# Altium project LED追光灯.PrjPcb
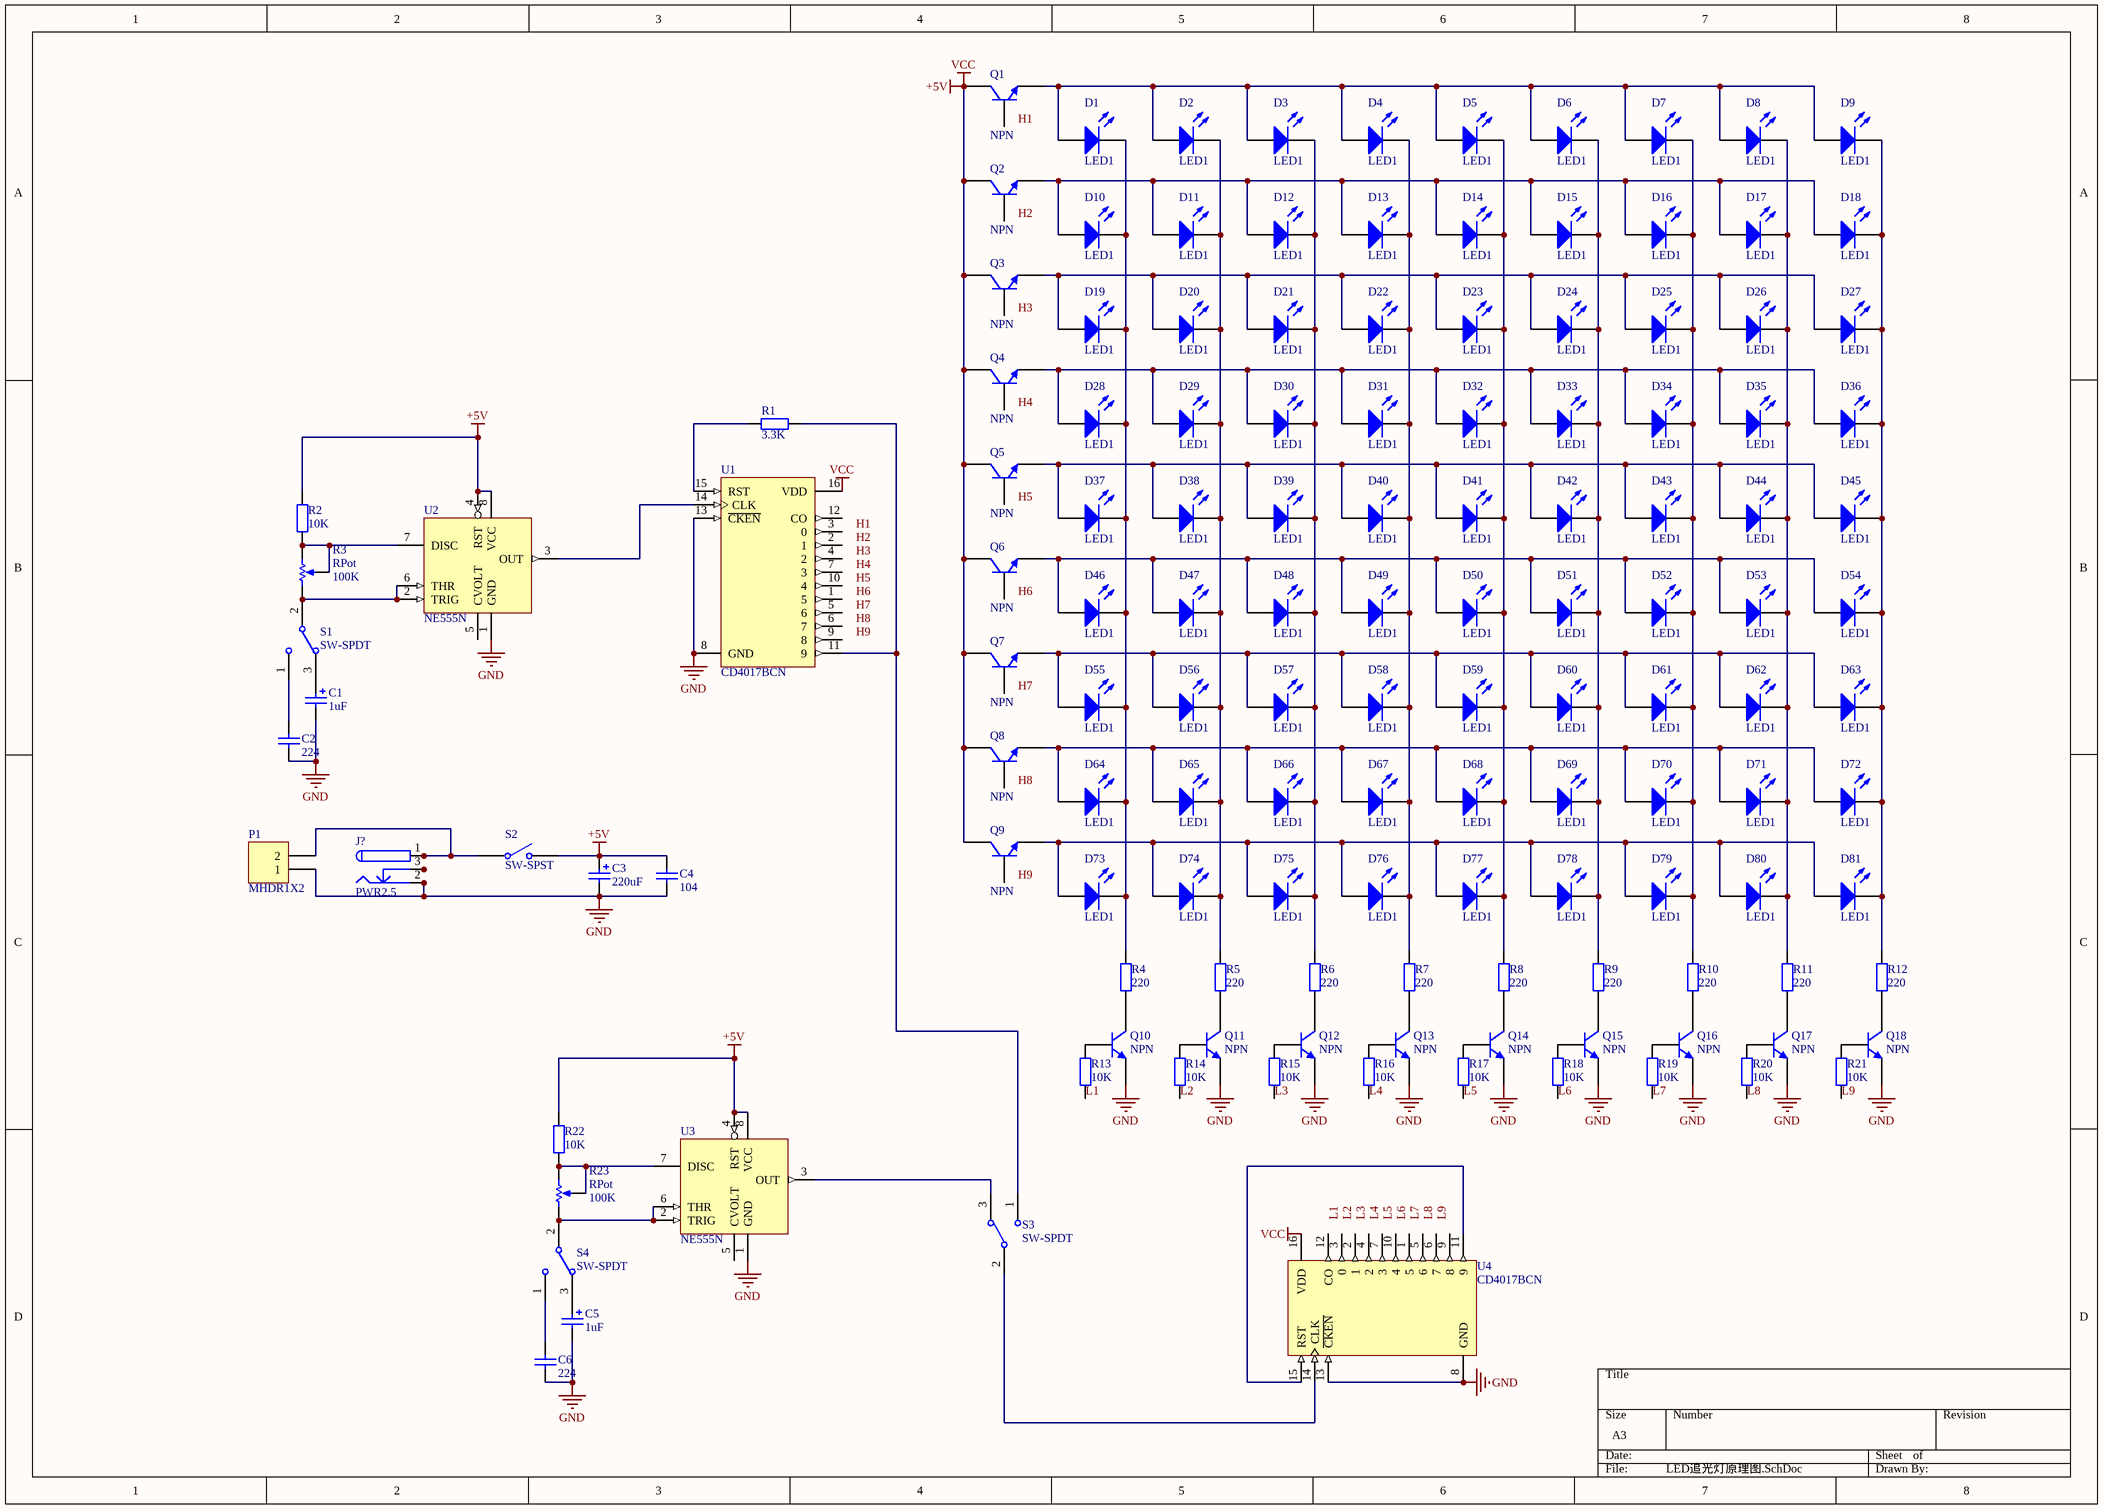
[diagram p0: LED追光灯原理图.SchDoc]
1 sheet, 138 parts. Net scope: global (net labels, ports and power ports of the same name join across sheets).
Board file: PCB1.PcbDoc

## Sheet LED追光灯原理图.SchDoc
size A3

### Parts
C1  value 1uF  [1uF电容器]  (hidden comment: Cap Pol2)
C2  value 224  [RAD-0.1]  (hidden comment: Cap)
C3  value 220uF  [220uF电容]  (hidden comment: Cap Pol2)
C4  value 104  [RAD-0.1]  (hidden comment: Cap)
C5  value 1uF  [1uF电容器]  (hidden comment: Cap Pol2)
C6  value 224  [RAD-0.1]  (hidden comment: Cap)
D1  LED1  [发光二极管]
D2  LED1  [发光二极管]
D3  LED1  [发光二极管]
D4  LED1  [发光二极管]
D5  LED1  [发光二极管]
D6  LED1  [发光二极管]
D7  LED1  [发光二极管]
D8  LED1  [发光二极管]
D9  LED1  [发光二极管]
D10  LED1  [发光二极管]
D11  LED1  [发光二极管]
D12  LED1  [发光二极管]
D13  LED1  [发光二极管]
D14  LED1  [发光二极管]
D15  LED1  [发光二极管]
D16  LED1  [发光二极管]
D17  LED1  [发光二极管]
D18  LED1  [发光二极管]
D19  LED1  [发光二极管]
D20  LED1  [发光二极管]
D21  LED1  [发光二极管]
D22  LED1  [发光二极管]
D23  LED1  [发光二极管]
D24  LED1  [发光二极管]
D25  LED1  [发光二极管]
D26  LED1  [发光二极管]
D27  LED1  [发光二极管]
D28  LED1  [发光二极管]
D29  LED1  [发光二极管]
D30  LED1  [发光二极管]
D31  LED1  [发光二极管]
D32  LED1  [发光二极管]
D33  LED1  [发光二极管]
D34  LED1  [发光二极管]
D35  LED1  [发光二极管]
D36  LED1  [发光二极管]
D37  LED1  [发光二极管]
D38  LED1  [发光二极管]
D39  LED1  [发光二极管]
D40  LED1  [发光二极管]
D41  LED1  [发光二极管]
D42  LED1  [发光二极管]
D43  LED1  [发光二极管]
D44  LED1  [发光二极管]
D45  LED1  [发光二极管]
D46  LED1  [发光二极管]
D47  LED1  [发光二极管]
D48  LED1  [发光二极管]
D49  LED1  [发光二极管]
D50  LED1  [发光二极管]
D51  LED1  [发光二极管]
D52  LED1  [发光二极管]
D53  LED1  [发光二极管]
D54  LED1  [发光二极管]
D55  LED1  [发光二极管]
D56  LED1  [发光二极管]
D57  LED1  [发光二极管]
D58  LED1  [发光二极管]
D59  LED1  [发光二极管]
D60  LED1  [发光二极管]
D61  LED1  [发光二极管]
D62  LED1  [发光二极管]
D63  LED1  [发光二极管]
D64  LED1  [发光二极管]
D65  LED1  [发光二极管]
D66  LED1  [发光二极管]
D67  LED1  [发光二极管]
D68  LED1  [发光二极管]
D69  LED1  [发光二极管]
D70  LED1  [发光二极管]
D71  LED1  [发光二极管]
D72  LED1  [发光二极管]
D73  LED1  [发光二极管]
D74  LED1  [发光二极管]
D75  LED1  [发光二极管]
D76  LED1  [发光二极管]
D77  LED1  [发光二极管]
D78  LED1  [发光二极管]
D79  LED1  [发光二极管]
D80  LED1  [发光二极管]
D81  LED1  [发光二极管]
J?  PWR2.5  [电源接口]
P1  MHDR1X2  [MHDR1X2]
Q1  NPN  [TO-92-3_L4.9-W3.7-P1.27-L]
Q2  NPN  [TO-92-3_L4.9-W3.7-P1.27-L]
Q3  NPN  [TO-92-3_L4.9-W3.7-P1.27-L]
Q4  NPN  [TO-92-3_L4.9-W3.7-P1.27-L]
Q5  NPN  [TO-92-3_L4.9-W3.7-P1.27-L]
Q6  NPN  [TO-92-3_L4.9-W3.7-P1.27-L]
Q7  NPN  [TO-92-3_L4.9-W3.7-P1.27-L]
Q8  NPN  [TO-92-3_L4.9-W3.7-P1.27-L]
Q9  NPN  [TO-92-3_L4.9-W3.7-P1.27-L]
Q10  NPN  [TO-92-3_L4.9-W3.7-P1.27-L]
Q11  NPN  [TO-92-3_L4.9-W3.7-P1.27-L]
Q12  NPN  [TO-92-3_L4.9-W3.7-P1.27-L]
Q13  NPN  [TO-92-3_L4.9-W3.7-P1.27-L]
Q14  NPN  [TO-92-3_L4.9-W3.7-P1.27-L]
Q15  NPN  [TO-92-3_L4.9-W3.7-P1.27-L]
Q16  NPN  [TO-92-3_L4.9-W3.7-P1.27-L]
Q17  NPN  [TO-92-3_L4.9-W3.7-P1.27-L]
Q18  NPN  [TO-92-3_L4.9-W3.7-P1.27-L]
R1  value 3.3K  [AXIAL-0.4]  (hidden comment: Res2)
R2  value 10K  [AXIAL-0.3]  (hidden comment: Res2)
R3  RPot  value 100K  [立式手柄电位器]
R4  value 220  [AXIAL-0.4]  (hidden comment: Res2)
R5  value 220  [AXIAL-0.4]  (hidden comment: Res2)
R6  value 220  [AXIAL-0.4]  (hidden comment: Res2)
R7  value 220  [AXIAL-0.4]  (hidden comment: Res2)
R8  value 220  [AXIAL-0.4]  (hidden comment: Res2)
R9  value 220  [AXIAL-0.4]  (hidden comment: Res2)
R10  value 220  [AXIAL-0.4]  (hidden comment: Res2)
R11  value 220  [AXIAL-0.4]  (hidden comment: Res2)
R12  value 220  [AXIAL-0.4]  (hidden comment: Res2)
R13  value 10K  [AXIAL-0.4]  (hidden comment: Res2)
R14  value 10K  [AXIAL-0.4]  (hidden comment: Res2)
R15  value 10K  [AXIAL-0.4]  (hidden comment: Res2)
R16  value 10K  [AXIAL-0.4]  (hidden comment: Res2)
R17  value 10K  [AXIAL-0.4]  (hidden comment: Res2)
R18  value 10K  [AXIAL-0.4]  (hidden comment: Res2)
R19  value 10K  [AXIAL-0.4]  (hidden comment: Res2)
R20  value 10K  [AXIAL-0.4]  (hidden comment: Res2)
R21  value 10K  [AXIAL-0.4]  (hidden comment: Res2)
R22  value 10K  [AXIAL-0.4]  (hidden comment: Res2)
R23  RPot  value 100K  [立式手柄电位器]
S1  SW-SPDT  [KEY-6]
S2  SW-SPST  [SPST-2]
S3  SW-SPDT  [KEY-6]
S4  SW-SPDT  [KEY-6]
U1  CD4017BCN  [cd4017]
U2  NE555N  [NE555]
U3  NE555N  [NE555]
U4  CD4017BCN  [cd4017]

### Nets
+5V: C3.1 C4.2 Q1.1(C) Q2.1(C) Q3.1(C) Q4.1(C) Q5.1(C) Q6.1(C) Q7.1(C) Q8.1(C) Q9.1(C) R2.1 R22.1 S2.2(NO) U1.16(VDD) U2.4(RST) U2.8(VCC) U3.4(RST) U3.8(VCC) U4.16(VDD)  [also labelled VCC]
GND: C1.2 C2.2 C3.2 C4.1 C5.2 C6.2 J?.2 J?.2A J?.2B P1.1 Q10.3(E) Q11.3(E) Q12.3(E) Q13.3(E) Q14.3(E) Q15.3(E) Q16.3(E) Q17.3(E) Q18.3(E) U1.8(GND) U1.13(~{CKEN}) U2.1(GND) U3.1(GND) U4.8(GND) U4.13(~{CKEN})
L1: R13.2
L2: R14.2
L3: R15.2
L4: R16.2
L5: R17.2
L6: R18.2
L7: R19.2
L8: R20.2
L9: R21.2
NetC1_1: C1.1 S1.3
NetC2_1: C2.1 S1.1
NetC5_1: C5.1 S4.3
NetC6_1: C6.1 S4.1
NetD1_1: D1.1(A) D2.1(A) D3.1(A) D4.1(A) D5.1(A) D6.1(A) D7.1(A) D8.1(A) D9.1(A) Q1.3(E)
NetD1_2: D1.2(K) D10.2(K) D19.2(K) D28.2(K) D37.2(K) D46.2(K) D55.2(K) D64.2(K) D73.2(K) R4.2
NetD2_2: D2.2(K) D11.2(K) D20.2(K) D29.2(K) D38.2(K) D47.2(K) D56.2(K) D65.2(K) D74.2(K) R5.2
NetD3_2: D3.2(K) D12.2(K) D21.2(K) D30.2(K) D39.2(K) D48.2(K) D57.2(K) D66.2(K) D75.2(K) R6.2
NetD4_2: D4.2(K) D13.2(K) D22.2(K) D31.2(K) D40.2(K) D49.2(K) D58.2(K) D67.2(K) D76.2(K) R7.2
NetD5_2: D5.2(K) D14.2(K) D23.2(K) D32.2(K) D41.2(K) D50.2(K) D59.2(K) D68.2(K) D77.2(K) R8.2
NetD6_2: D6.2(K) D15.2(K) D24.2(K) D33.2(K) D42.2(K) D51.2(K) D60.2(K) D69.2(K) D78.2(K) R9.2
NetD7_2: D7.2(K) D16.2(K) D25.2(K) D34.2(K) D43.2(K) D52.2(K) D61.2(K) D70.2(K) D79.2(K) R10.2
NetD8_2: D8.2(K) D17.2(K) D26.2(K) D35.2(K) D44.2(K) D53.2(K) D62.2(K) D71.2(K) D80.2(K) R11.2
NetD9_2: D9.2(K) D18.2(K) D27.2(K) D36.2(K) D45.2(K) D54.2(K) D63.2(K) D72.2(K) D81.2(K) R12.2
NetD10_1: D10.1(A) D11.1(A) D12.1(A) D13.1(A) D14.1(A) D15.1(A) D16.1(A) D17.1(A) D18.1(A) Q2.3(E)
NetD19_1: D19.1(A) D20.1(A) D21.1(A) D22.1(A) D23.1(A) D24.1(A) D25.1(A) D26.1(A) D27.1(A) Q3.3(E)
NetD28_1: D28.1(A) D29.1(A) D30.1(A) D31.1(A) D32.1(A) D33.1(A) D34.1(A) D35.1(A) D36.1(A) Q4.3(E)
NetD37_1: D37.1(A) D38.1(A) D39.1(A) D40.1(A) D41.1(A) D42.1(A) D43.1(A) D44.1(A) D45.1(A) Q5.3(E)
NetD46_1: D46.1(A) D47.1(A) D48.1(A) D49.1(A) D50.1(A) D51.1(A) D52.1(A) D53.1(A) D54.1(A) Q6.3(E)
NetD55_1: D55.1(A) D56.1(A) D57.1(A) D58.1(A) D59.1(A) D60.1(A) D61.1(A) D62.1(A) D63.1(A) Q7.3(E)
NetD64_1: D64.1(A) D65.1(A) D66.1(A) D67.1(A) D68.1(A) D69.1(A) D70.1(A) D71.1(A) D72.1(A) Q8.3(E)
NetD73_1: D73.1(A) D74.1(A) D75.1(A) D76.1(A) D77.1(A) D78.1(A) D79.1(A) D80.1(A) D81.1(A) Q9.3(E)
NetJ?_1: J?.1 J?.1A J?.1B P1.2 S2.1(COMMON)
NetJ?_3: J?.3 J?.3A J?.3B
NetQ10_1: Q10.1(C) R4.1
NetQ10_2: Q10.2(B) R13.1
NetQ11_1: Q11.1(C) R5.1
NetQ11_2: Q11.2(B) R14.1
NetQ12_1: Q12.1(C) R6.1
NetQ12_2: Q12.2(B) R15.1
NetQ13_1: Q13.1(C) R7.1
NetQ13_2: Q13.2(B) R16.1
NetQ14_1: Q14.1(C) R8.1
NetQ14_2: Q14.2(B) R17.1
NetQ15_1: Q15.1(C) R9.1
NetQ15_2: Q15.2(B) R18.1
NetQ16_1: Q16.1(C) R10.1
NetQ16_2: Q16.2(B) R19.1
NetQ17_1: Q17.1(C) R11.1
NetQ17_2: Q17.2(B) R20.1
NetQ18_1: Q18.1(C) R12.1
NetQ18_2: Q18.2(B) R21.1
NetR1_1: R1.1 U1.15(RST)
NetR1_2: R1.2 S3.1 U1.11(9)
NetR2_2: R2.2 R3.2(BOT) R3.3(TAP) U2.7(DISC)
NetR3_1: R3.1(TOP) S1.2 U2.2(TRIG) U2.6(THR)
NetR22_2: R22.2 R23.2(BOT) R23.3(TAP) U3.7(DISC)
NetR23_1: R23.1(TOP) S4.2 U3.2(TRIG) U3.6(THR)
NetS3_2: S3.2 U4.14(CLK)
NetS3_3: S3.3 U3.3(OUT)
NetU1_14: U1.14(CLK) U2.3(OUT)
NetU4_11: U4.11(9) U4.15(RST)

Not connected (* = marked no-connect by the designer): Q1 2(B); Q2 2(B); Q3 2(B); Q4 2(B); Q5 2(B); Q6 2(B); Q7 2(B); Q8 2(B); Q9 2(B); U1 1(5) 2(1) 3(0) 4(2) 5(6) 6(7) 7(3) 9(8) 10(4) 12(CO); U2 5(CVOLT); U3 5(CVOLT); U4 1(5) 2(1) 3(0) 4(2) 5(6) 6(7) 7(3) 9(8) 10(4) 12(CO)

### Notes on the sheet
- Labels drawn without touching a wire or pin: H1, H2, H3, H4, H5, H6, H7, H8, H9, L1, L2, L3, L4, L5, L6, L7, L8, L9

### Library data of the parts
C1 C3 C5 = Cap Pol2: Polarized Capacitor (Axial)
C2 C4 C6 = Cap: Capacitor
D1-D81 = LED1: Typical RED GaAs LED
J? = PWR2.5: Low Voltage Power Supply Connector
P1 = MHDR1X2: Header, 2-Pin
Q1-Q18 = NPN: NPN Bipolar Transistor
R1 R2 R4-R22 = Res2: Resistor
R3 R23 = RPot: Potentiometer; Sim Note: Enter the Resistance value and the set point into parameter fields.; Set Position: 0.5
S1 S3 S4 = SW-SPDT: SPDT Subminiature Toggle Switch, Right Angle Mounting, Vertical Actuation
S2 = SW-SPST: Single-Pole, Single-Throw Switch
U1 U4 = CD4017BCN: Decade Counter/Divider with 10 Decoded Outputs
U2 U3 = NE555N: General-Purpose Single Bipolar Timer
